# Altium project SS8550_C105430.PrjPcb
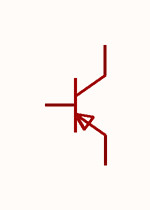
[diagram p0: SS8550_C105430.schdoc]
1 sheet, 1 parts. Net scope: global (net labels, ports and power ports of the same name join across sheets).

## Sheet SS8550_C105430.schdoc
size 127 x 101 mm

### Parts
Q?  ss8550(range:120-200)  [SOT-23-3_L2.9-W1.6-P1.90-LS2.8-BR]  (value not drawn)

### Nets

Not connected (* = marked no-connect by the designer): Q? 1 2 3

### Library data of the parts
Q? = ss8550(range:120-200): 晶体管类型:PNP;集电极电流(Ic):1.5A;集射极击穿电压(Vceo):25V;耗散功率(Pd):300mW;直流电流增益(hFE):120;; Manufacturer: CJ(江苏长电/长晶); Symbol: SS8550_C105430; AddInBom: yes; ModelId: 89cb27a44ab2466697082bb9fd73a7d0; ModelName: SOT-23-3L_L2.9-W1.6-H1.1-LS2.8-P0.95; ModelTransform: 114.173,110.236,0,90,0,0,0,0,0; type: PNP; Current - Collector(Ic): 1.5A; Collector - Emitter Voltage VCEO: 25V; Pd - Power Dissipation: 300mW; DC Current Gain: 120; Transition frequency(fT): 100MHz; Current - Collector Cutoff: 100nA; Vce Saturation(VCE(sat)): 500mV; Emitter-Base Voltage(Vebo): 5V; Number: 1个PNP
